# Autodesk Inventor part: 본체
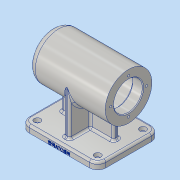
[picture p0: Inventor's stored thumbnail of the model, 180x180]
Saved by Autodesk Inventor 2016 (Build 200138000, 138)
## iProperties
Created: 2020-10
Part Number: 본체
Material: 알루미늄 6061
Document SubType Name: Modeling
Designer: user
Mass: 1026.28 g
Surface Area: 757.984 cm^2
Volume: 380.103 cm^3
Density: 2.7 g/cm^3
Appearance: 알루미늄 - 평지
Author: user
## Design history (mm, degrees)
sketch "스케치1"
  geometry: C1 r 34 at (0, 0); 1 further point
  constraints: 1 centre point, 1 coincident
extrude "돌출1" new body sketch "스케치1" stored distance "d0" = 112; taper "d1" = 0 deg
node "작업 평면1"
node "스케치3"
sketch "스케치4"
  geometry: L1 (56, 45)-(-56, 45); L2 (-56, 45)-(-56, -45); L3 (-56, -45)-(56, -45); L4 (56, -45)-(56, 45); L5 (56, 45)-(-56, -45); L6 (-56, 45)-(56, -45); 1 further point
  constraints: 12 end point, 2 midpoint, 2 parallel, 1 horizontal, 1 perpendicular
extrude "돌출2" join sketch "스케치4" distance "d22" = 10; taper "d23" = 0 deg
sketch "스케치5"
  geometry: L1 (-56, -45)-(-56, 45) reference; L2 (-56, 45)-(56, 45) reference; L3 (56, 45)-(56, -45) reference; L4 (56, -45)-(-56, -45) reference; L5 (-38, 4)-(38, 4); L6 (38, 4)-(38, -4); L7 (38, -4)-(-38, -4); L8 (-38, -4)-(-38, 4); 2 further points
  constraints: 8 end point, 2 parallel, 1 horizontal, 1 horizontal alignment, 1 midpoint, 1 perpendicular
  dimensions: "d24" = 8 distance of L5.end L6.end; "d25" = 18 distance between parallel lines of L6 L3; "d26" = 18 distance between parallel lines of L8 L1
extrude "돌출3" join sketch "스케치5" stored distance "d27" = 10; taper "d28" = 0 deg
fillet "모깎기3" dims "d29" = 10
sketch "스케치6"
  geometry: L1 (38, 4)-(38, -4) reference; L2 (38, -4)-(-38, -4) reference; L3 (-38, -4)-(-38, 4) reference; L4 (-38, 4)-(38, 4) reference; L5 (-56, -45)-(-56, 45) reference; L6 (-56, 45)-(56, 45) reference; L7 (56, 45)-(56, -45) reference; L8 (56, -45)-(-56, -45) reference; L9 (4, -34)-(-4, -34); L10 (-4, -34)-(-4, 34); L11 (-4, 34)-(4, 34); L12 (4, 34)-(4, -34); L13 (4, -34)-(-4, 34); L14 (-4, -34)-(4, 34); 1 further point
  constraints: 12 end point, 2 midpoint, 2 parallel, 1 horizontal, 1 perpendicular
extrude "돌출4" join sketch "스케치6" stored distance "d30" = 10; taper "d31" = 0 deg
fillet "모깎기4" dims "d32" = 3
fillet "모깎기5" dims "d33" = 3
fillet "모깎기6" dims "d34" = 12
fillet "모깎기7" dims "d35" = 3
sketch "스케치7"
  geometry: L1 (44, 45)-(-44, 45) reference; L2 (56, -33)-(56, 33) reference; L3 (-44, -45)-(44, -45) reference; L4 (-56, 33)-(-56, -33) reference; A1 r 12 centre (-44, 33) between (-44, 45) and (-56, 33) reference; A2 r 12 centre (44, 33) between (56, 33) and (44, 45) reference; A3 r 12 centre (44, -33) between (44, -45) and (56, -33) reference; A4 r 12 centre (-44, -33) between (-56, -33) and (-44, -45) reference; 5 further points
  constraints: 4 coincident
hole "구멍1" sketch "스케치7" at (-44, 33), (44, 33), (44, -33), (-44, -33) diameter "d36" = 5.5; stored, may be unused: countersink angle "d40" = 90 deg, drill point angle "d42" = 118 deg; dims "d37" = 6, "d38" = 4, "d39" = 2, "d41" = 8
sketch "스케치8"
  geometry: L1 (44, 45)-(-44, 45) reference; L2 (56, -33)-(56, 33) reference; L3 (-44, -45)-(44, -45) reference; L4 (-56, 33)-(-56, -33) reference; C1 r 2.75 at (44, -33) reference; C2 r 2.75 at (-44, 33) reference; C3 r 2.75 at (44, 33) reference; C4 r 2.75 at (-44, -33) reference; C5 r 2.75 at (-44, -33) reference; A1 r 12 centre (-44, 33) between (-44, 45) and (-56, 33) reference; A2 r 12 centre (44, 33) between (56, 33) and (44, 45) reference; A3 r 12 centre (44, -33) between (44, -45) and (56, -33) reference; A4 r 12 centre (-44, -33) between (-56, -33) and (-44, -45) reference; 5 further points
  constraints: 4 coincident
hole "구멍2" sketch "스케치8" at (-44, 33), (44, 33), (44, -33), (-44, -33) diameter "d43" = 9.5; stored, may be unused: countersink angle "d47" = 90 deg, drill point angle "d49" = 0 deg; dims "d44" = 6, "d45" = 4, "d46" = 2, "d48" = 5.4
node "스케치9"
sketch "스케치10"
  geometry: L1 (-33, -67)-(33, -67) reference; L2 (33, -74)-(33, -67) reference; L3 (33, -74)-(-33, -74) reference; L4 (-33, -74)-(-33, -67) reference; C1 r 34 at (0, 0) reference; 4 further points
  constraints: 2 vertical alignment, 1 coincident, 2 other
hole "구멍3" sketch "스케치10" at (0, 26) diameter "d50" = 3.242; stored, may be unused: countersink angle "d54" = 90 deg, drill point angle "d56" = 118 deg; dims "d51" = 8, "d52" = 4, "d53" = 2, "d55" = 11
sketch "스케치11"
  geometry: 1 further point
sketch "스케치12"
  geometry: L1 (-46, 34)-(56, 34) reference; L2 (56, 34)-(56, 27.621) reference; L3 (56, 27.621)-(45, 27.621) reference; L4 (45, 27.621)-(44.026, 26) reference; L5 (44.026, 26)-(45, 24.379) reference; L6 (45, 24.379)-(56, 24.379) reference; L7 (56, 24.379)-(56, -24.379) reference; L8 (56, -24.379)-(45, -24.379) reference; L9 (45, -24.379)-(44.026, -26) reference; L10 (44.026, -26)-(45, -27.621) reference; L11 (45, -27.621)-(56, -27.621) reference; L12 (56, -27.621)-(56, -34) reference; L13 (56, -34)-(41, -34) reference; L14 (38, -37)-(38, -61) reference; L15 (41, -64)-(53, -64) reference; L16 (56, -67)-(56, -74) reference; L17 (56, -74)-(-56, -74) reference; L18 (-56, -74)-(-56, -67) reference; L19 (-53, -64)-(-41, -64) reference; L20 (-38, -61)-(-38, -37) reference; L21 (-41, -34)-(-46, -34) reference; L22 (-56, -24)-(-56, 24) reference; L23 (56, 0)-(41, 0); L24 (41, 0)-(41, 21); L25 (41, 21)-(56, 21); L26 (56, 21)-(56, 0); L27 (41, 0)-(-13, 0); L28 (-13, 0)-(-13, 24); L29 (-13, 24)-(41, 24); L30 (41, 24)-(41, 0); L31 (-13, 0)-(-25, 0); L32 (-25, 0)-(-25, 21); L33 (-25, 21)-(-13, 21); L34 (-13, 21)-(-13, 0); L35 (-25, 0)-(-43, 0); L36 (-43, 0)-(-43, 17.5); L37 (-43, 17.5)-(-25, 17.5); L38 (-25, 17.5)-(-25, 0); L39 (-43, 0)-(-47, 0); L40 (-47, 0)-(-47, 16); L41 (-47, 16)-(-43, 16); L42 (-43, 16)-(-43, 0); L43 (-47, 0)-(-50, 0); L44 (-50, 0)-(-50, 10.5); L45 (-50, 10.5)-(-47, 10.5); L46 (-47, 10.5)-(-47, 0); A1 r 3 centre (41, -37) between (41, -34) and (38, -37) reference; A2 r 3 centre (41, -61) between (38, -61) and (41, -64) reference; A3 r 3 centre (53, -67) between (56, -67) and (53, -64) reference; A4 r 3 centre (-53, -67) between (-53, -64) and (-56, -67) reference; A5 r 3 centre (-41, -61) between (-41, -64) and (-38, -61) reference; A6 r 3 centre (-41, -37) between (-38, -37) and (-41, -34) reference; A7 r 10 centre (-46, -24) between (-56, -24) and (-46, -34) reference; A8 r 10 centre (-46, 24) between (-46, 34) and (-56, 24) reference; 1 further point
  constraints: 48 end point, 12 parallel, 6 horizontal, 6 perpendicular, 1 midpoint
  dimensions: "d60" = 42 diameter of L25 L23; "d61" = 48 diameter of L29 L27; "d62" = 42 diameter of L33 L31; "d63" = 35 diameter of L37 L35; "d64" = 32 diameter of L41 L39; "d65" = 21 diameter of L45 L43; "d66" = 3 distance of L44.end L45.end; "d67" = 4 distance of L40.end L41.end; "d68" = 18 distance of L36.end L37.end; "d69" = 12 distance of L32.end L33.end; "d70" = 54 distance of L28.end L29.end; "d71" = 15 distance of L24.end L25.end
revolve "회전2" sketch "스케치12" stored, may be unused: angle "d72" = 90 deg
fillet "모깎기8" dims "d73" = 0.3
fillet "모깎기9" dims "d74" = 3
fillet "모깎기10" dims "d75" = 3
chamfer "모따기2" distance "d76" = 1; stored, may be unused: second distance "d77" = 2, angle "d78" = 45 deg
sketch "스케치13"
  geometry: L1 (0, 0)-(88, 0) reference; L2 (100, 0)-(100, 7) reference; 2 further points
  constraints: 1 other
  dimensions: "d79" = 3 distance from line of L1 point (44, 3); "d80" = 56 distance from line of L2 point (44, 3)
feature "엠보싱1" sketch "스케치13" dims "d0" = 112, "d1" = 0, "d81" = 0.5, "d82" = 0
node "솔리드1"
pattern_circular "원형 패턴1" dims angle "d58" = 360 deg
node "투영된 루프1"
node "투영된 루프2"
node "절단 모서리 투영2"
node "절단 모서리 투영3"
node "절단 모서리 투영4"
node "절단 모서리 투영5"
other parameters: "d21" = -74
